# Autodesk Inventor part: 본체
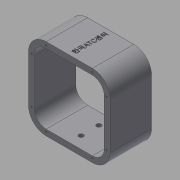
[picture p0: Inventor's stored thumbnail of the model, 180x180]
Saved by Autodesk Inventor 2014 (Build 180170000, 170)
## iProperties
Created: 2016-12
Part Number: 본체
Material: 일반
Document SubType Name: Modeling
Designer: mduedu
Density: 1 g/cm^3
Appearance: 기본값
Mass: 325.956 g
Surface Area: 772.714 cm^2
Volume: 325.956 cm^3
Author: mduedu
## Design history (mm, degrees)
sketch "스케치1"
  geometry: L1 (-46, 42)-(-46, -36); L2 (-16, 72)-(62, 72); L3 (92, 42)-(92, -36); L4 (62, -66)-(-16, -66); A1 r 30 centre (-16, -36) between (-46, -36) and (-16, -66); A2 r 30 centre (62, 42) between (92, 42) and (62, 72); A3 r 30 centre (62, -36) between (62, -66) and (92, -36); A4 r 30 centre (-16, 42) between (-16, 72) and (-46, 42); 1 further point
  constraints: 8 end point, 8 point on circle, 8 tangent, 4 centre point, 3 equal radius, 1 horizontal, 1 perpendicular, 1 vertical
  dimensions: "d83" = 30 radius of A2; "d84" = 92 distance from line of L3 point (0, 0); "d85" = 138 distance between parallel lines of L4 L2; "d86" = 46 distance from line of L1 point (0, 0); "d87" = 72 distance from line of point (0, 0) L2
extrude "돌출1" new body sketch "스케치1" stored distance "d3" = 70; taper "d4" = 0 deg
feature "쉘1" dims "d5" = 10
sketch "스케치10"
  geometry: L1 (78, 70)-(0, 70) reference; L2 (-30, 70)-(-30, 0) reference; 4 further points
  constraints: 1 coincident, 1 horizontal alignment, 1 midpoint, 1 vertical alignment, 1 other
  dimensions: "d88" = 35 distance of point (39, 35) point (39, 70) (derived); "d89" = 69 distance from line of point (39, 35) L2 (derived)
feature "엠보싱1" sketch "스케치10" dims "d61" = 0.5, "d62" = 0, "d83" = 30, "d84" = 92, "d85" = 138, "d86" = 46, "d87" = 72
sketch "스케치11"
  geometry: L1 (-36, -36)-(-36, 42) reference; L2 (-16, 62)-(62, 62) reference; L3 (82, 42)-(82, -36) reference; L4 (62, -56)-(-16, -56) reference; L5 (-16, -66)-(62, -66) reference; L6 (92, -36)-(92, 42) reference; L7 (62, 72)-(-16, 72) reference; L8 (-46, 42)-(-46, -36) reference; L9 (-16, 66)-(62, 66); L10 (86, 42)-(86, -36); L11 (62, -60)-(-16, -60); L12 (-40, -36)-(-40, 42); A1 r 20 centre (-16, -36) between (-36, -36) and (-16, -56) reference; A2 r 20 centre (-16, 42) between (-16, 62) and (-36, 42) reference; A3 r 20 centre (62, 42) between (82, 42) and (62, 62) reference; A4 r 20 centre (62, -36) between (62, -56) and (82, -36) reference; A5 r 30 centre (-16, -36) between (-46, -36) and (-16, -66) reference; A6 r 30 centre (62, -36) between (62, -66) and (92, -36) reference; A7 r 30 centre (62, 42) between (92, 42) and (62, 72) reference; A8 r 30 centre (-16, 42) between (-16, 72) and (-46, 42) reference; A9 r 24 centre (62, 42) between (86, 42) and (62, 66); A10 r 24 centre (62, -36) between (62, -60) and (86, -36); A11 r 24 centre (-16, -36) between (-40, -36) and (-16, -60); A12 r 24 centre (-16, 42) between (-16, 66) and (-40, 42); 8 further points
  constraints: 8 coincident, 8 end point, 8 point on circle, 4 centre point, 7 other
  dimensions: "d90" = 6 distance between parallel lines of L9 L7
hole "구멍3" sketch "스케치11" at (-16, 66), (-40, 42), (-40, -36), (-16, -60), (62, -60), (86, -36), (86, 42), (62, 66) diameter "d63" = 3.242; stored, may be unused: countersink angle "d67" = 90 deg, drill point angle "d69" = 120 deg; dims "d64" = 8.6, "d65" = 4, "d66" = 2, "d68" = 10.6
sketch "스케치12"
  geometry: L1 (16, -56)-(-62, -56) reference; L2 (-82, -36)-(-82, 42) reference; L3 (-62, 62)-(16, 62) reference; L4 (36, 42)-(36, -36) reference; L5 (46, -36)-(46, 42) reference; L6 (16, 72)-(-62, 72) reference; L7 (-92, 42)-(-92, -36) reference; L8 (-62, -66)-(16, -66) reference; L9 (-62, 66)-(16, 66); L10 (40, 42)-(40, -36); L11 (16, -60)-(-62, -60); L12 (-86, -36)-(-86, 42); A1 r 20 centre (16, -36) between (16, -56) and (36, -36) reference; A2 r 20 centre (-62, -36) between (-82, -36) and (-62, -56) reference; A3 r 20 centre (-62, 42) between (-62, 62) and (-82, 42) reference; A4 r 20 centre (16, 42) between (36, 42) and (16, 62) reference; A5 r 30 centre (16, -36) between (16, -66) and (46, -36) reference; A6 r 30 centre (16, 42) between (46, 42) and (16, 72) reference; A7 r 30 centre (-62, 42) between (-62, 72) and (-92, 42) reference; A8 r 30 centre (-62, -36) between (-92, -36) and (-62, -66) reference; A9 r 24 centre (16, 42) between (40, 42) and (16, 66); A10 r 24 centre (16, -36) between (16, -60) and (40, -36); A11 r 24 centre (-62, -36) between (-86, -36) and (-62, -60); A12 r 24 centre (-62, 42) between (-62, 66) and (-86, 42); 8 further points
  constraints: 8 coincident, 8 end point, 8 point on circle, 4 centre point, 7 other
  dimensions: "d91" = 6 distance between parallel lines of L9 L6
hole "구멍5" sketch "스케치12" at (-62, 66), (-86, 42), (-86, -36), (-62, -60), (16, -60), (40, -36), (40, 42), (16, 66) diameter "d70" = 3.242; stored, may be unused: countersink angle "d74" = 90 deg, drill point angle "d76" = 120 deg; dims "d71" = 8.6, "d72" = 4, "d73" = 2, "d75" = 10.6
sketch "스케치15"
  geometry: L1 (135.6, -35)-(-57.6, -35) reference; L2 (78, 0)-(0, 0) reference; L3 (0, -70)-(78, -70) reference; L4 (39, 0)-(39, -70); C1 r 4 at (39, -20); C2 r 4 at (39, -50); 1 further point
  constraints: 2 centre point, 2 end point, 2 midpoint, 1 point on line, 1 symmetric about line, 1 other
  dimensions: "d92" = 8 diameter of C1; "d93" = 15 distance from line of C1.centre L1
extrude "돌출6" cut sketch "스케치15" stored distance "d94" = 10; taper "d95" = 0 deg
node "솔리드1"
node "투영된 루프3"
node "투영된 루프4"
